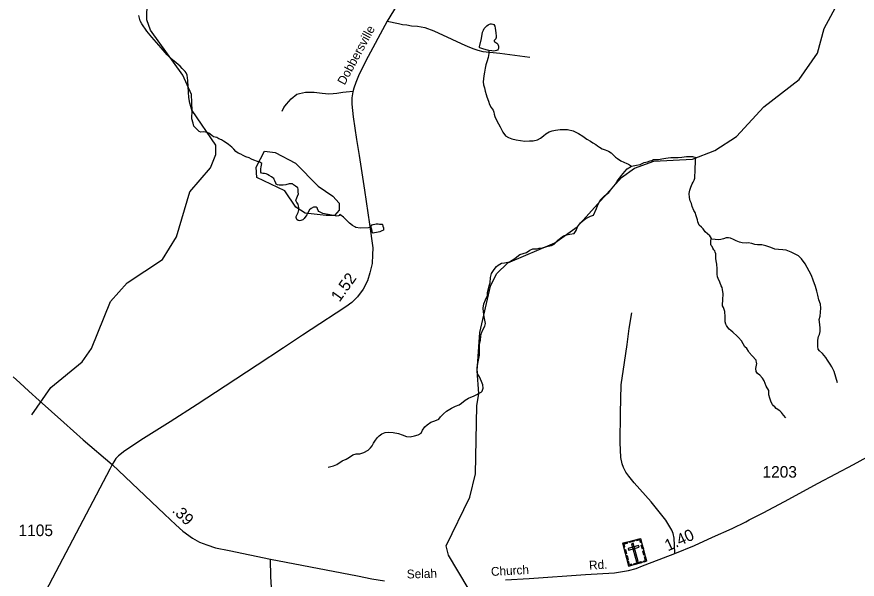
# Model space of a CAD drawing. Extents: x 2206922 to 2357709, y 510027 to 673830.
# Drawn here: x 2232663 to 2241724, y 569592 to 575657 of the extents above; entities that cross this region are included whole.
import ezdxf

# ---------------------------------------------------------------- set-up
doc = ezdxf.new("R2010")
doc.units = 0
for name, color, linetype in [('Exist Cultural Cemetery CELL', 7, 'Continuous'), ('Exist Hydrographic Creek Single Shore', 7, 'Continuous'), ('Exist Hydrographic Misc Water Feature', 7, 'Continuous'), ('Exist Hydrographic Pond Under 1500 Sq Ft', 7, 'Continuous'), ('Exist Road Non-System Type 51', 7, 'Continuous'), ('Exist Road Secondary Mileage Hundredths English Label', 7, 'Continuous'), ('Exist Road Secondary Type 51 Attributed', 7, 'Continuous'), ('Exist Road Secondary Type 51 Label', 7, 'Continuous'), ('Exist Road Secondary Type 51 Number Label', 7, 'Continuous')]:
    doc.layers.add(name, color=color, linetype=linetype)

msp = doc.modelspace()

# ---------------------------------------------------------------- linework, layer by layer
at = {"layer": 'Exist Cultural Cemetery CELL'}
for points in [[(2239195.7, 569979.8), (2239388.1, 570031), (2239453.6, 569785), (2239261.3, 569733.7)], [(2239267.3, 569998.8), (2239317.4, 570012.2), (2239320.3, 570001.1), (2239270.2, 569987.8)], [(2239399.3, 569989.1), (2239388.3, 569986.2), (2239380.1, 570017.3), (2239340.9, 570006.9), (2239338, 570017.6), (2239388.1, 570031)], [(2239206.8, 569937.9), (2239217.8, 569940.8), (2239209.5, 569971.9), (2239248.7, 569982.4), (2239245.9, 569993.1), (2239195.7, 569979.8)], [(2239225.9, 569866.2), (2239214.8, 569908.1), (2239225.8, 569911), (2239236.9, 569869.2)], [(2239252.7, 569924.5), (2239257.5, 569906.5), (2239371.2, 569936.8), (2239366.4, 569954.8)], [(2239308.6, 569979.5), (2239290.5, 569974.7), (2239342.8, 569778.8), (2239360.8, 569783.6)], [(2239407.1, 569915.6), (2239395.9, 569957.4), (2239406.9, 569960.4), (2239418.1, 569918.5)], [(2239243.2, 569801.3), (2239232.1, 569843.1), (2239243.1, 569846.1), (2239254.2, 569804.2)], [(2239424, 569851.9), (2239412.9, 569893.7), (2239423.9, 569896.7), (2239435, 569854.8)], [(2239421.6, 569776.4), (2239418.7, 569787.5), (2239439.9, 569793.2), (2239429.5, 569832.3), (2239440.3, 569835.1), (2239453.6, 569785)], [(2239293.2, 569742.3), (2239290.3, 569753.4), (2239269, 569747.7), (2239258.6, 569786.8), (2239247.8, 569783.9), (2239261.2, 569733.7)], [(2239313.8, 569759.6), (2239395.8, 569781.4), (2239398.8, 569770.4), (2239316.8, 569748.6)]]:
    msp.add_lwpolyline(points, close=True, dxfattribs=at)
at = {"layer": 'Exist Hydrographic Creek Single Shore'}
msp.add_lwpolyline([(2232824.2, 571364), (2233030.1, 571658.3), (2233369.1, 571936.8), (2233468.1, 572079.1), (2233672.1, 572586.7), (2233854.2, 572789.6), (2234235.2, 573041.1), (2234383.2, 573284), (2234529.2, 573769.8), (2234751.1, 574027.6), (2234808.1, 574170.8), (2234808.1, 574272.5), (2234555.1, 574644.9), (2234545.2, 574819), (2234452.1, 575027.5), (2234106.2, 575513.3), (2234064.2, 575622.5), (2234076.1, 576212.6), (2233940.1, 576520.3), (2233745.1, 576868.7), (2233713.9, 577240.7)], dxfattribs=at)
at = {"layer": 'Exist Hydrographic Misc Water Feature'}
for points in [[(2238829, 573531), (2239183.1, 573924.9), (2239324.2, 574023.7), (2239532.3, 574101.5), (2239948.2, 574122.7), (2240189.3, 574216.2), (2240421.2, 574365.6), (2240718.1, 574684.3), (2241099.3, 574981.6), (2241297.2, 575266.2), (2241369.2, 575530.5), (2241582.2, 575932.9), (2241644.1, 576535.1), (2241642.3, 576807.4)], [(2234840.1, 574342.6), (2234818.4, 574354.4), (2234784.1, 574364), (2234764, 574378), (2234731.8, 574401.5), (2234715.6, 574409.6), (2234679.5, 574415.1), (2234647.4, 574413), (2234627.5, 574420.9), (2234613.7, 574432.7), (2234573.3, 574478.1), (2234562.9, 574508.1), (2234550.6, 574556.2), (2234550.2, 574589.9), (2234552, 574616), (2234554.1, 574638), (2234539.7, 574690), (2234527.4, 574723.9), (2234516.9, 574785.5), (2234512, 574901.5), (2234507.1, 574969.5), (2234500.9, 575029.2), (2234488.4, 575051.3), (2234478.8, 575067), (2234446.2, 575101.1), (2234425.9, 575124.9), (2234380, 575160.2), (2234323.4, 575208.1), (2234283.2, 575247.4), (2234218.4, 575320.8), (2234167.9, 575380.3), (2234117.7, 575436.2), (2234063.2, 575501.6), (2234012.7, 575581.4), (2233994.7, 575612.9), (2233977.9, 575671)], [(2237753.3, 575293.7), (2237736.9, 575297.8), (2237698.9, 575307.2), (2237654.9, 575322.8), (2237650.7, 575327), (2237650.7, 575334.7), (2237672.1, 575421.2), (2237685.2, 575493), (2237693.4, 575511.2), (2237701, 575529.1), (2237715.1, 575545.2), (2237729.1, 575559.4), (2237744.7, 575569.6), (2237760.7, 575577.7), (2237770.7, 575579.8), (2237780.8, 575582), (2237794.7, 575577.9), (2237805.2, 575572.2), (2237815.2, 575556.1), (2237821.1, 575536.1), (2237827.5, 575482.4), (2237832.2, 575448.5), (2237832.2, 575438.3), (2237829.8, 575434.2), (2237828.1, 575424.4), (2237826.3, 575418.2), (2237812.3, 575406.1), (2237808.4, 575400.2), (2237808, 575396.1), (2237810.5, 575390.1), (2237816.2, 575386.4), (2237838.2, 575372.6), (2237848.4, 575360.5), (2237852.7, 575350.5), (2237856.8, 575338.5), (2237856.8, 575328.4), (2237854.8, 575314.5), (2237851.1, 575306.5), (2237844.9, 575298.5), (2237833.2, 575292.2), (2237818.9, 575290.3), (2237799, 575288), (2237783.2, 575290), (2237753.3, 575293.7)], [(2237753.3, 575293.7), (2237751.4, 575262), (2237743.4, 575219.8), (2237729.9, 575169.5), (2237720.5, 575139.7), (2237712.7, 575103.6), (2237704.7, 575061.4), (2237697.7, 575021.5), (2237693.6, 574989.3), (2237692.2, 574957.4), (2237696.3, 574921.5), (2237704.5, 574891.5), (2237712.7, 574853.8), (2237722.7, 574819.8), (2237731.1, 574793.8), (2237747.7, 574747.9), (2237759.6, 574712), (2237778.1, 574680), (2237798.4, 574648.6), (2237804.3, 574628.6), (2237808.6, 574608.5), (2237816.8, 574580.5), (2237839.4, 574535), (2237857.6, 574501), (2237875.5, 574471.1), (2237901.9, 574413.2), (2237930.2, 574373.6), (2237962.6, 574353.8), (2237998.5, 574342.3), (2238046.9, 574328.5), (2238092.8, 574323.2), (2238141, 574317.5), (2238190.9, 574317.7), (2238229.2, 574318), (2238276.8, 574330.3), (2238308.1, 574348.7), (2238340.3, 574373), (2238366.2, 574393.1), (2238403.9, 574415.3), (2238435.7, 574427.6), (2238472, 574435.9), (2238520, 574440.4), (2238557.7, 574442.9), (2238601.6, 574441.1), (2238659.6, 574427.5), (2238718, 574397.9), (2238764.2, 574368.3), (2238810.3, 574337), (2238848.3, 574317.1), (2238874.7, 574299.3), (2238904.4, 574281.5), (2238924.7, 574265.8), (2238946.7, 574251.9), (2238973.1, 574232.2), (2239005.1, 574222.5), (2239041.6, 574208.9), (2239071.4, 574188.9), (2239089.6, 574171.2), (2239117.7, 574143.4), (2239138, 574127.4), (2239176.1, 574103.8), (2239208.1, 574088.1), (2239238.5, 574076.6), (2239256.7, 574066.5), (2239288.7, 574046.7)], [(2235306.4, 574076.4), (2235282.4, 574088.1), (2235258, 574097.9), (2235217.8, 574111.6), (2235193.8, 574123.4), (2235167.8, 574135), (2235133.5, 574147.1), (2235102, 574160.8), (2235077.3, 574174.6), (2235049.5, 574188.1), (2235025.3, 574206), (2235001.1, 574229.9), (2234981, 574251.6), (2234944.9, 574279.4), (2234920.5, 574297.2), (2234892.4, 574316.8), (2234870.4, 574330.7), (2234840.1, 574342.6)], [(2239288.7, 574046.7), (2239344.5, 574055.3), (2239384.7, 574063.5), (2239428.3, 574084), (2239464.2, 574092.4), (2239491.7, 574102.5), (2239508.1, 574108.5), (2239528.2, 574116.8), (2239549.7, 574118.8), (2239579.7, 574119.2), (2239617.8, 574123.6), (2239661.7, 574132), (2239685.7, 574136), (2239715.4, 574138.1), (2239747.2, 574138.5), (2239793.7, 574138.8), (2239831.5, 574143.3), (2239857.5, 574147.4), (2239883.6, 574149.6), (2239909.4, 574151.8), (2239947.7, 574150), (2239983.6, 574140.6)], [(2240148.3, 573274.3), (2240134.1, 573295.9), (2240109.7, 573315.8), (2240085.7, 573337.7), (2240061.8, 573369.3), (2240045.3, 573389.1), (2240021.4, 573411), (2240007, 573446.9), (2240000.9, 573468.9), (2239988.3, 573510.9), (2239976.2, 573544.8), (2239963.9, 573566.5), (2239943.6, 573612.1), (2239937.5, 573642.3), (2239923.3, 573674), (2239914.9, 573710.1), (2239912.7, 573750.2), (2239918, 573788), (2239929.9, 573818.2), (2239943.4, 573854.2), (2239955.9, 573872.2), (2239967.6, 573894.4), (2239973, 573916.3), (2239974.8, 573940.4), (2239976.7, 573984.3), (2239976.5, 574028.5), (2239979.7, 574082.4), (2239979.7, 574110.4), (2239983.6, 574140.6)], [(2236146.3, 573523.5), (2236140.3, 573513.5), (2236130.3, 573509.2), (2236112.7, 573507.1), (2235962.1, 573535.9), (2235940, 573545.7), (2235919.9, 573557.6), (2235912.3, 573567.7), (2235903.7, 573585.6), (2235899.8, 573597.6), (2235891.4, 573603.3), (2235875.6, 573605.3), (2235861.7, 573603.3), (2235835.8, 573591), (2235820, 573574.8), (2235802.2, 573544.6), (2235788.5, 573520.7), (2235780.9, 573508.5), (2235762.8, 573482.4), (2235746.8, 573468.1), (2235724.7, 573460.1), (2235710.8, 573458.2), (2235697, 573459.9), (2235683.1, 573469.7), (2235676.9, 573481.6), (2235674.7, 573491.6), (2235676.7, 573503.5), (2235684.7, 573525.8), (2235696.4, 573548), (2235704.2, 573573.9), (2235703.8, 573600), (2235701.7, 573615.7), (2235695.4, 573635.7), (2235683.5, 573653.7), (2235675.5, 573667.5), (2235671.4, 573677.4), (2235675.1, 573687.4), (2235688.8, 573721.8), (2235698.7, 573747.5), (2235698.2, 573765.8), (2235698.2, 573783.7), (2235696, 573797.8), (2235691.9, 573811.8), (2235668.1, 573831.6), (2235647.8, 573845.2), (2235633.7, 573855.1), (2235614, 573856.8), (2235598, 573854.8), (2235563.9, 573846.6), (2235536, 573840.2), (2235513.9, 573840.3), (2235492.2, 573841.9), (2235474.1, 573845.9), (2235465.9, 573847.9), (2235460, 573853.7), (2235455.7, 573863.7), (2235445.6, 573889.5), (2235439.5, 573901.4), (2235433.1, 573911.7), (2235423.3, 573921.3), (2235407.5, 573931.3), (2235383.1, 573945.2), (2235367.3, 573954.9), (2235351.1, 573965), (2235333.5, 573968.5), (2235317.3, 573968.5), (2235302.9, 573972.3), (2235294.9, 573982.4), (2235292.7, 573992.5), (2235294.7, 574016.5), (2235298.2, 574038.3), (2235306.4, 574076.4)], [(2237681.1, 571618.8), (2237692.8, 571651.1), (2237686.4, 571689), (2237674.1, 571724.9), (2237651.8, 571774.5), (2237631.5, 571808.3), (2237627, 571870.3), (2237634.6, 571916.6), (2237642.5, 571954.3), (2237652, 572008.4), (2237651.8, 572034.4), (2237651.2, 572084.4), (2237653, 572124.3), (2237660.8, 572170.5), (2237666.3, 572216.3), (2237673.9, 572246.4), (2237683.8, 572272.5), (2237709.6, 572320.9), (2237714.9, 572350.9), (2237702.2, 572422.6), (2237694.2, 572476.5), (2237689.5, 572514.5), (2237699.3, 572562.5), (2237717, 572604.9), (2237736.9, 572653), (2237738.3, 572684.8), (2237747.9, 572725.1), (2237755.7, 572756.8), (2237767.6, 572789.1), (2237770.9, 572844.9), (2237781, 572889.3), (2237808.2, 572931.4), (2237834.1, 572963.6), (2237851.7, 572977.5), (2237887.8, 573000.1), (2237919.8, 573004.2), (2237975.1, 573014.9), (2238031.1, 573049), (2238053.3, 573067.2), (2238086.9, 573093.3), (2238120.7, 573105.6), (2238156.6, 573116.1), (2238194.5, 573140.3), (2238226.3, 573154.6), (2238268, 573154.8), (2238294, 573161), (2238332.1, 573165.4), (2238365.8, 573175.7), (2238391.8, 573184), (2238426.1, 573192.2), (2238457.6, 573206.5), (2238497.4, 573248.7), (2238558.9, 573293.4), (2238594.8, 573305.4), (2238626.8, 573313.6), (2238672.5, 573320.1), (2238692.4, 573352.4), (2238708.4, 573392.5), (2238741.8, 573434.5), (2238769.5, 573458.7), (2238797.4, 573482.9), (2238849.3, 573505.5), (2238881.1, 573517.8), (2238912.6, 573590), (2238923.9, 573617.9), (2238934, 573639.9), (2238953.7, 573678.3), (2238973.3, 573702.5), (2238999.2, 573724.6), (2239044.7, 573761.1), (2239062.7, 573787.2), (2239118.1, 573851.4), (2239135.7, 573883.6), (2239159.7, 573917.7), (2239183.7, 573944.1), (2239219, 573988.3), (2239244.4, 574018.5), (2239288.7, 574046.7)], [(2236483.2, 573386.3), (2236453.7, 573380.2), (2236365.5, 573377.3), (2236317.5, 573384.9), (2236307.5, 573390.9), (2236283.5, 573404.7), (2236250.7, 573430.3), (2236204.7, 573478.2), (2236184.6, 573497.9), (2236146.3, 573523.5)], [(2238487.2, 567385.9), (2238442.3, 567754.2), (2238348.1, 568087.4), (2237831.2, 568156.8), (2237780.1, 568230), (2237648.3, 569187.1), (2237529.2, 569494.6), (2237317.1, 569853), (2237292.1, 569952), (2237546.2, 570478.2), (2237610.1, 570729.4), (2237621.2, 571460.6), (2237645.2, 571594.6), (2237626.1, 571837.7), (2237656.3, 572253.6), (2237769.3, 572753.1), (2237834.3, 572886.3), (2237958.1, 573005.1), (2238464.2, 573217.9), (2238705.1, 573393.4), (2238829, 573531)], [(2236483.2, 573386.3), (2236487.1, 573412.5), (2236495.1, 573414.5), (2236504.9, 573418.3), (2236523.2, 573422.5), (2236537.1, 573424.8), (2236558.8, 573422.7), (2236574.8, 573421.1), (2236590.8, 573421.1), (2236602.9, 573421.4), (2236606.8, 573417.1), (2236611.1, 573399.4), (2236615.2, 573381.3), (2236617.5, 573371.3), (2236617.7, 573359.5), (2236615.2, 573355.4), (2236599.4, 573347.3), (2236575.7, 573337.1), (2236539.8, 573330.8), (2236517.8, 573326.8), (2236503.9, 573324.4), (2236499.6, 573326.7), (2236493.6, 573344.6), (2236489.3, 573362.3), (2236483.2, 573386.3)], [(2240953.7, 571331.6), (2240929.9, 571359.5), (2240907.6, 571389.3), (2240891, 571407.2), (2240851, 571434.7), (2240835, 571450.5), (2240822.7, 571460.5), (2240810.8, 571476.5), (2240794.4, 571502.5), (2240780.5, 571544.3), (2240771.8, 571582.1), (2240769.4, 571626.3), (2240742.9, 571674), (2240720.8, 571729.7), (2240704.4, 571759.3), (2240672.4, 571791.3), (2240650.3, 571810.9), (2240642, 571821.1), (2240633.8, 571830.8), (2240631.6, 571862.8), (2240641, 571916.9), (2240637.1, 571926.8), (2240633, 571953), (2240592.4, 572002.5), (2240560.2, 572036.2), (2240550.2, 572050.3), (2240533.8, 572079.9), (2240513.9, 572097.9), (2240475.1, 572163.3), (2240445, 572197.1), (2240429, 572212.9), (2240382.2, 572254.8), (2240362.8, 572272.3), (2240344.5, 572290.1), (2240328.5, 572306.3), (2240320.1, 572318.1), (2240313.8, 572328), (2240308, 572341.8), (2240301.9, 572365.9), (2240301.5, 572419.9), (2240294.9, 572479.7), (2240280.5, 572521.6), (2240271.9, 572541.5), (2240270.3, 572551.5), (2240275.8, 572603.4), (2240279.3, 572667.7), (2240270.7, 572715.6), (2240266.8, 572737.4), (2240256.6, 572755.5), (2240242.2, 572797), (2240226.2, 572833.1), (2240218, 572853), (2240213.3, 572880.9), (2240215.3, 572938.9), (2240210.8, 572990.7), (2240206.5, 573006.8), (2240198.3, 573048.6), (2240197.9, 573068.9), (2240199.8, 573100.7), (2240193.8, 573118.6), (2240187.4, 573134.6), (2240179.5, 573144.3), (2240167.1, 573160.4), (2240159.2, 573178.2), (2240148.7, 573190.3), (2240147.1, 573200.3), (2240144.8, 573220.1), (2240144.8, 573230.2), (2240148.3, 573274.3)], [(2241512.3, 571710.1), (2241493.8, 571770), (2241475.6, 571831.6), (2241448.9, 571883.4), (2241432.7, 571911.4), (2241404.4, 571955.1), (2241386.2, 571982.9), (2241350.1, 572024.5), (2241315.9, 572056.4), (2241303.5, 572072), (2241299.4, 572100.3), (2241299.2, 572128.2), (2241298.8, 572168.1), (2241306.2, 572208.3), (2241318.3, 572232), (2241324.1, 572264.4), (2241323.6, 572300.2), (2241319.3, 572338.1), (2241315.2, 572391.9), (2241324.7, 572428.2), (2241326.5, 572470), (2241332, 572516.3), (2241327.7, 572556.3), (2241309.3, 572606.1), (2241299.2, 572655.9), (2241288.8, 572697.6), (2241274, 572747.6), (2241249.6, 572817.5), (2241231.2, 572867.3), (2241207, 572913.1), (2241184.4, 572954.6), (2241162.3, 572992.8), (2241121.5, 573046.4), (2241089.5, 573078), (2241047.4, 573101.8), (2241011.3, 573119.4), (2240957.2, 573138.9), (2240921.1, 573144.4), (2240875, 573146.1), (2240835.2, 573151.6), (2240791.1, 573167.6), (2240738.6, 573186.9), (2240696.8, 573198.5), (2240650.5, 573196.1), (2240620.9, 573202.2), (2240588.9, 573211.9), (2240549, 573219.6), (2240526.8, 573217.2), (2240484.8, 573219.1), (2240454.4, 573226.9), (2240418.5, 573240.4), (2240388.6, 573254.3), (2240356.4, 573268.1), (2240334.5, 573273.8), (2240310.7, 573271.7), (2240280.5, 573261.2), (2240254.3, 573255), (2240226.4, 573252.8), (2240192.6, 573256.7), (2240156.7, 573260.5), (2240148.3, 573274.3)], [(2236018.3, 570801.8), (2236078.6, 570814.2), (2236112.4, 570830.7), (2236171.9, 570867.1), (2236213.5, 570887.6), (2236251.5, 570907.4), (2236287.4, 570934.1), (2236323.4, 570944), (2236361.4, 570942.4), (2236403.2, 570958.8), (2236451, 570983.2), (2236476.6, 571007.3), (2236494.5, 571029.3), (2236510.2, 571057.7), (2236529.9, 571091.7), (2236551.7, 571120), (2236571.2, 571138.2), (2236597.4, 571158.1), (2236633.5, 571172.6), (2236674.9, 571176.9), (2236721.2, 571173.6), (2236779.5, 571163.6), (2236819.5, 571148.2), (2236863.6, 571132.6), (2236905.4, 571128.7), (2236949.3, 571137.1), (2236989.3, 571147.3), (2237021, 571167.7), (2237036.8, 571197.7), (2237062.2, 571234), (2237086.4, 571258.4), (2237125.8, 571286.5), (2237170.1, 571298.9), (2237211.7, 571319.3), (2237231.6, 571341.5), (2237263.2, 571375.7), (2237295.2, 571404.1), (2237348.9, 571438.2), (2237394.4, 571458.9), (2237432.4, 571473), (2237456.4, 571489.3), (2237495.7, 571521.5), (2237533.9, 571543.7), (2237595.2, 571570.1), (2237669.2, 571608.8), (2237681.1, 571618.8)]]:
    msp.add_lwpolyline(points, dxfattribs=at)
at = {"layer": 'Exist Hydrographic Pond Under 1500 Sq Ft'}
msp.add_lwpolyline([(2235997.2, 573513.8), (2235771.2, 573538), (2235671.2, 573602.3), (2235553.1, 573778.5), (2235252.1, 573925.7), (2235243.2, 574034.1), (2235333.3, 574209.3), (2235450.1, 574193.9), (2235667.1, 574078), (2235911.1, 573830.4), (2236070.2, 573722.2), (2236137.3, 573648.7), (2236138.1, 573573.2), (2236088.3, 573515.2), (2235997.2, 573513.8)], dxfattribs=at)
at = {"layer": 'Exist Road Non-System Type 51'}
for points in [[(2236657.5, 575610.5), (2236778, 575585), (2236821.9, 575573.3), (2236869.4, 575568.6), (2236917.4, 575560.8), (2236981.5, 575555.3), (2237061.5, 575540.1), (2237157.8, 575505), (2237352.3, 575414.4), (2237454.7, 575367.4), (2237526.9, 575335.9), (2237591.1, 575310.5), (2237635.2, 575296.8), (2237687.4, 575283.3), (2237869.3, 575264.9), (2238193.6, 575221.5)], [(2235525.5, 574638.1), (2235543.2, 574680.1), (2235568.9, 574716.4), (2235622.4, 574770.7), (2235682, 574821.2), (2235710, 574829.5), (2235775.8, 574843.9), (2235867.6, 574844.7), (2235955.8, 574833.5), (2236025.8, 574826.2), (2236073.7, 574830.3), (2236111.7, 574832.8), (2236179.5, 574845.1), (2236215.4, 574849.5), (2236288.9, 574854.4)], [(2239758.4, 569870.8), (2239753.7, 569958.6), (2239751.1, 570034.7), (2239740.7, 570086.5), (2239724.4, 570120.4), (2239659.6, 570227.9), (2239504.1, 570426.5), (2239318.5, 570632.8), (2239260, 570704.4), (2239229.5, 570748), (2239203.2, 570795.9), (2239188.9, 570837.6), (2239176.2, 570903.6), (2239166.9, 571067.4), (2239170.3, 571383.2), (2239179.8, 571687.1), (2239213.9, 571927.4), (2239244.2, 572123.5), (2239266.9, 572295.6), (2239295.5, 572463.7)]]:
    msp.add_lwpolyline(points, dxfattribs=at)
at = {"layer": 'Exist Road Secondary Type 51 Attributed'}
for points in [[(2237096.6, 576334.5), (2236656.5, 575608.8), (2236425.3, 575182.2), (2236348.1, 575018.7), (2236317.5, 574948.6), (2236296, 574885.7), (2236287, 574846.2), (2236276.2, 574781.5), (2236276.2, 574715), (2236290.6, 574576.6), (2236326.5, 574334), (2236355.2, 574159.7), (2236410.9, 573787.7), (2236466.6, 573419.3), (2236502.5, 573164.1), (2236498.9, 573088.6), (2236493.5, 572995.2), (2236468.4, 572896.4), (2236443.2, 572810.1), (2236396.5, 572718.4), (2236337.3, 572637.6), (2236276.2, 572576.5), (2236209.8, 572529.7), (2236105.6, 572459.7), (2235929.6, 572346.4), (2235744.6, 572222.4), (2235538, 572085.9), (2235254.3, 571900.8), (2234909.4, 571672.5), (2234607.7, 571476.7), (2234314.9, 571289.8), (2234029.4, 571108.3), (2233828.2, 570976), (2233758.6, 570923.4), (2233730.8, 570893.4), (2233707.3, 570857), (2233690.2, 570829.9)], [(2232623.1, 571773.2), (2232696.7, 571710.3), (2232793.7, 571620.4), (2232905.1, 571518), (2233169.1, 571280.8), (2233379.2, 571095.7), (2233690.2, 570829.9)], [(2237931.6, 569586), (2238187.4, 569600.2), (2238794.7, 569643.1), (2239108.5, 569661.6), (2239257.6, 569686.8), (2239340.2, 569708.3), (2239408.5, 569737.1), (2239512.7, 569776.6), (2239758.4, 569870.8), (2239969.6, 569956.5), (2240164.8, 570046.1), (2240376, 570139.6), (2240522, 570211.5), (2240559.7, 570233.1), (2240708.8, 570308.6), (2240938.7, 570429), (2241301.6, 570626.9), (2241683.8, 570829.9), (2242010.1, 571010.5)], [(2233690.2, 570829.9), (2233665.9, 570778.7), (2232899.9, 569321.9), (2232569.5, 568682.9), (2232436, 568443.3), (2232353.5, 568284), (2232292.2, 568175.7), (2232215.5, 568018.4), (2232163.7, 567885), (2232115.8, 567734.4), (2232052.5, 567569.5), (2231995, 567400.7), (2231964.3, 567306.7), (2231947.9, 567198.5), (2231927.8, 566956.4), (2231912.9, 566568.4), (2231901.1, 566306.5), (2231887.7, 565992.5), (2231876.1, 565887.1), (2231832, 565647.3)], [(2233690.2, 570829.9), (2234255.7, 570292.4), (2234377.8, 570177.4), (2234453.2, 570109.1), (2234555.6, 570034.3), (2234633.9, 569991), (2234710.1, 569963.5), (2234803.5, 569931.2), (2234954.3, 569902.4), (2235397, 569807.4)], [(2235411.9, 569449.6), (2235400.6, 569619.4), (2235397, 569807.4)], [(2235397, 569807.4), (2236166.6, 569659.8), (2236336.1, 569629.1), (2236490.2, 569596.3), (2236626.3, 569575.4)]]:
    msp.add_lwpolyline(points, dxfattribs=at)

# ---------------------------------------------------------------- texts
at = {"layer": 'Exist Road Secondary Mileage Hundredths English Label'}
for s, rotation, p in [('1.52', 54.37124, (2236141.9, 572574.3)), ('.39', 315.97958, (2234329.2, 570323.9)), ('1.40', 24.65582, (2239683.1, 569891.2))]:
    msp.add_text(s, height=125, rotation=rotation, dxfattribs=at).set_placement(p)
at = {"layer": 'Exist Road Secondary Type 51 Label'}
for s, rotation, p in [('Dobbersville', 61.81512, (2236197.5, 574914.1)), ('Church', 3.17723, (2237778, 569626.7)), ('Rd.', 3.37404, (2238835.3, 569694.8)), ('Selah', 1.51358, (2236869.1, 569599.6))]:
    msp.add_text(s, height=95, rotation=rotation, dxfattribs=at).set_placement(p)
at = {"layer": 'Exist Road Secondary Type 51 Number Label'}
for s, p in [('1203', (2240702.1, 570687.2)), ('1105', (2232681.6, 570057))]:
    msp.add_text(s, height=125, dxfattribs=at).set_placement(p)

doc.saveas('drawing.dxf')
